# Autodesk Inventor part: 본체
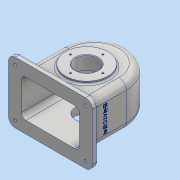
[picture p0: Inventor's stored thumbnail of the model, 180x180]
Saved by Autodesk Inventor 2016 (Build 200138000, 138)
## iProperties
Created: 2018-11
Part Number: 본체
Material: 알루미늄 6061
Document SubType Name: Modeling
Designer: user
Mass: 1092.35 g
Surface Area: 1180.61 cm^2
Volume: 404.572 cm^3
Density: 2.7 g/cm^3
Appearance: 알루미늄 - 평지
Author: user
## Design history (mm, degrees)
sketch "스케치3"
  geometry: L1 (75, 55)-(-75, 55); L2 (-75, 55)-(-75, -55); L3 (-75, -55)-(75, -55); L4 (75, -55)-(75, 55); L5 (75, 55)-(-75, -55); L6 (-75, 55)-(75, -55); 1 further point
  constraints: 12 end point, 2 midpoint, 2 parallel, 1 horizontal, 1 perpendicular
  dimensions: "d3" = 110 distance of L3.end L1.start; "d4" = 150 distance of L2.end L3.end
extrude "돌출1" new body sketch "스케치3" distance "d5" = 10; taper "d6" = 0 deg
sketch "스케치4"
  geometry: L1 (-75, 0)-(75, 0) reference; L2 (-75, 10)-(75, 10) reference; L3 (-58, 78)-(-58, 10); L4 (58, 78)-(58, 10); A1 r 58 centre (0, 78) between (-58, 78) and (58, 78); 2 further points
  constraints: 4 end point, 2 perpendicular, 2 point on circle, 2 point on line, 2 tangent, 1 centre point, 1 midpoint, 1 vertical alignment
  dimensions: "d7" = 116 diameter of A1; "d11" = 136 dimension on A1 L1
extrude "돌출2" join sketch "스케치4" stored distance "d12" = 77; taper "d13" = 0 deg
feature "쉘1" dims "d16" = 10, "d17" = 5, "d30" = 6
sketch "스케치6"
  geometry: L1 (-75, 0)-(75, 0) reference; C1 r 38 at (0, 65); 2 further points
  constraints: 1 centre point, 1 midpoint, 1 vertical alignment
  dimensions: "d18" = 65 distance from line of L1 C1.centre; "d19" = 76 diameter of C1
extrude "돌출3" join sketch "스케치6" distance "d20" = 5; taper "d21" = 0 deg
node "작업 평면2"
sketch "스케치12"
  geometry: L1 (52, -78)-(-52, -78) reference; C1 r 28 at (0, -13); 2 further points
  constraints: 1 centre point, 1 midpoint, 1 vertical alignment
  dimensions: "d36" = 65 distance from line of L1 C1.centre; "d37" = 56 diameter of C1
extrude "돌출7" join sketch "스케치12" distance "d38" = 14; taper "d39" = 40 deg
sketch "스케치13"
  geometry: C1 r 20 at (0, 0); C2 r 38 at (0, 0) reference; 1 further point
  constraints: 1 centre point, 1 concentric
  dimensions: "d40" = 40 diameter of C1
extrude "돌출8" cut sketch "스케치13" distance "d41" = 24; taper "d42" = 0 deg
node "작업 평면3"
sketch "스케치14"
  geometry: C1 r 6 at (0, 0); 1 further point
  constraints: 1 centre point, 1 coincident
  dimensions: "d44" = 12 diameter of C1
extrude "돌출9" join sketch "스케치14" stored distance "d45" = 24; taper "d46" = 5 deg
sketch "스케치17"
  geometry: 1 further point
hole "구멍3" sketch "스케치17" at (0, 0) diameter "d62" = 4.459; stored, may be unused: countersink angle "d66" = 90 deg, drill point angle "d68" = 118 deg; dims "d63" = 10, "d64" = 4, "d65" = 2, "d67" = 12.8
sketch "스케치18"
  geometry: L1 (75, -55)-(75, 55) reference; L2 (-75, -55)-(75, -55) reference; C1 r 6 at (63, -43); 1 further point
  constraints: 1 centre point
  dimensions: "d72" = 12 distance from line of C1.centre L1; "d73" = 12 distance from line of L2 C1.centre; "d74" = 12 diameter of C1
extrude "돌출10" cut sketch "스케치18" distance "d75" = 4; taper "d76" = 0 deg
sketch "스케치19"
  geometry: C1 r 2.5 at (63, -43); C2 r 6 at (63, -43) reference; 1 further point
  constraints: 1 centre point, 1 concentric
  dimensions: "d77" = 5 diameter of C1
extrude "돌출11" cut sketch "스케치19" distance "d78" = 10; taper "d79" = 0 deg
fillet "모깎기1" dims "d86" = 12
fillet "모깎기2" dims "d87" = 3
fillet "모깎기3" dims "d88" = 13
fillet "모깎기4" dims "d89" = 3
fillet "모깎기5" dims "d90" = 3
fillet "모깎기6" dims "d91" = 8
sketch "스케치20"
  geometry: L1 (-17.5, -78)-(68.5, -78) reference; L2 (-13, 0)-(-13, -65) reference; 2 further points
  constraints: 1 other
  dimensions: "d92" = 40 distance from line of L1 point (25.5, -38); "d93" = 38.5 distance from line of L2 point (25.5, -38)
feature "엠보싱1" sketch "스케치20" dims "d3" = 110, "d4" = 150, "d94" = 0.5, "d95" = 0
sketch "스케치21"
  geometry: L1 (-63, 0)-(63, 0) reference; C1 r 38 at (0, 65); 2 further points
  constraints: 1 centre point, 1 midpoint, 1 vertical alignment
  dimensions: "d96" = 65 distance from line of L1 C1.centre; "d97" = 76 diameter of C1
extrude "돌출12" join sketch "스케치21" distance "d98" = 10; taper "d99" = 0 deg
sketch "스케치22"
  geometry: C1 r 20 at (0, 0); C2 r 38 at (0, 0) reference; 1 further point
  constraints: 1 centre point, 1 concentric
  dimensions: "d100" = 40 diameter of C1
extrude "돌출13" cut sketch "스케치22" distance "d101" = 18.5; taper "d102" = 0 deg
sketch "스케치23"
  geometry: C1 r 20 at (0, 0) reference; 2 further points
  constraints: 1 vertical alignment
  dimensions: "d103" = 29 distance of C1.centre point (0, 29)
hole "구멍4" sketch "스케치23" at (0, 29) diameter "d104" = 3.242; stored, may be unused: countersink angle "d108" = 90 deg, drill point angle "d110" = 118 deg; dims "d105" = 8, "d106" = 4, "d107" = 2, "d109" = 10
chamfer "모따기1" distance "d114" = 1; stored, may be unused: second distance "d115" = 2, angle "d116" = 45 deg
fillet "모깎기7" dims "d117" = 3
node "솔리드1"
pattern_linear "직사각형 패턴1" dims "d82" = 86, "d85" = 126
pattern_circular "원형 패턴2" dims angle "d112" = 360 deg
mirror "대칭4"
other parameters: "d35" = 14, "d43" = 142
